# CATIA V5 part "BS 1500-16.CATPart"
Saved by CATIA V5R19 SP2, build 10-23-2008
Part number: BS 1500-16
Bounding box of the stored display mesh (mm): x -31.459 to 31.459, y -31.459 to 31.459, z 0 to 76
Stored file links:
  C:\Users\Bora\Desktop\3D Katı model\BS serisi\BS 1500\BS 1500-16.CATPart
  C:\Program Files\Dassault Systemes\B19\intel_a\reffiles\standard\MetricThickPitch.txt
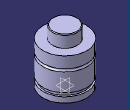
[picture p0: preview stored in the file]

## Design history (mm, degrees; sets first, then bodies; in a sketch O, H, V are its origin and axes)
Body1 (main body)
  Sketch1 on yz-plane, origin (0, 0, 0), H (0, 1, 0), V (0, 0, 1)
    point P1 (31.5, 43)
    point P2 (31.5, 39)
    point P3 (31.5, 43)
    point P7 (18, 75)
    point P9 (18, 75)
    point P14 (31.5, 39)
    arc A1 centre (31.5, 41) radius 2 from (31.5, 43) to (31.5, 39) ccw
    line L1 (31.5, 43) -> (31.5, 59)
    line L2 (31.5, 0) -> (31.5, 8)
    arc A2 centre (17, 75) radius 1 from (18, 75) to (17, 76) ccw
    line L3 (18, 75) -> (18, 59)
    line L4 (29, 13) -> (29, 8)
    line L5 (31.5, 13) -> (31.5, 39)
    line L6 (17, 76) -> (0, 76)
    point P15 (0, 76)
    line L7 (18, 59) -> (31.5, 59)
    line L8 (0, 0) -> (31.5, 0)
    line L9 (29, 13) -> (31.5, 13)
    line L10 (29, 8) -> (31.5, 8)
    tangency: L6 A2
    coincidence: P15 V, P1 P3, P2 P14, P7 P9
    horizontal: L7 H, L8 H, L9 H, L10 H
  Shaft1: profile Sketch1, axis Sketch1.V, angle 360
  Sketch2 on face of Shaft1 from Sketch1.L8, origin (0, 0, 0), H (1, 0, 0), V (0, -1, 0)
    point P1 (10, 0)
    distance P1 V = 10
  Hole1: placed by Sketch2, at (10, 0, 0) direction (0, 0, 1), diameter 6.647, depth 5, threaded "M8", thread diameter 8, thread depth 5, pitch 1.25
  CircPattern1: of Hole1, instances 2, angular step 180, axis from xy-plane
